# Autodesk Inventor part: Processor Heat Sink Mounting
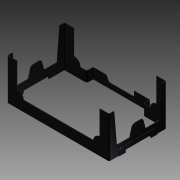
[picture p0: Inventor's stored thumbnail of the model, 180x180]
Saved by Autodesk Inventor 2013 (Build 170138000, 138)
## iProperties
Company: Autodesk Inc.
Created: 2005-11
Part Number: Processor Heat Sink Mounting
Document SubType Name: Modeling
Designer: Autodesk Inc.
Density: 1 g/cm^3
Mass: 1.74353 g
Surface Area: 69.5144 cm^2
Volume: 1.74353 cm^3
Material: Allgemein
Title: Personal Computer
Author: Autodesk Inc.
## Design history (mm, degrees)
sketch "Sketch1"
  geometry: L1 (0, 37.5)-(0, -32.5) reference; L2 (-56, 0)-(56, 0) reference; L3 (-40, 22.5)-(40, 22.5); L4 (40, 22.5)-(40, -22.5); L5 (40, -22.5)-(-40, -22.5); L6 (-40, -22.5)-(-40, 22.5); L7 (-22.5, 22.5)-(22.5, 22.5); L8 (22.5, 22.5)-(22.5, 27.5); L9 (22.5, 27.5)-(-22.5, 27.5); L10 (-22.5, 27.5)-(-22.5, 22.5)
  constraints: 16 end point, 4 parallel, 2 horizontal, 2 perpendicular, 1 point on line, 3 other
  dimensions: "d0" = 80 distance of L3.start L3.end; "d1" = 45 distance of L5.end L3.start; "d2" = 45 distance of L8.end L9.end; "d3" = 5 distance of L9.end L7.start
extrude "Extrusion1" new body sketch "Sketch1" distance "d4" = 32; taper "d5" = 0 deg
fillet "Fillet2" dims "d22" = 1
shell "Shell1" dims "d6" = 0.5
sketch "Sketch2"
  geometry: L1 (80, 32)-(0, 32) reference; L2 (0, 0)-(80, 0) reference; L3 (80, 0)-(80, 32) reference; L4 (7.5, 32)-(7.5, 13); L5 (12.5, 8)-(67.5, 8); L6 (72.5, 13)-(72.5, 32); L7 (7.5, 13)-(24.006, 13); L8 (12.5, 8)-(12.5, 12.458); L9 (72.5, 13)-(51.974, 13); L10 (67.5, 8)-(67.5, 19.427); L11 (40, 38.4)-(40, -6.4) reference; A1 r 5 centre (7.5, 8) between (12.5, 8) and (7.5, 13); A2 r 5 centre (72.5, 8) between (72.5, 13) and (67.5, 8)
  constraints: 14 end point, 6 perpendicular, 4 point on circle, 4 tangent, 3 point on line, 2 centre point, 2 parallel, 1 symmetric about line, 2 other
  dimensions: "d7" = 8 distance between parallel lines of L2 L5; "d8" = 65 distance between parallel lines of L6 L4; "d9" = 5 radius of A1
extrude "Extrusion2" cut sketch "Sketch2" stored distance "d10" = 32; taper "d11" = 0 deg
sketch "Sketch3"
  geometry: L1 (-32, 45)-(-32, 0) reference; L2 (0, 0)-(0, 45) reference; L3 (0, 45)-(-32, 45) reference; L4 (-38.4, 22.5)-(6.4, 22.5) reference; L5 (-32, 41)-(-8, 38.9); L6 (-8, 38.9)-(-8, 28.644); L7 (-8, 28.644)-(-16, 26.5); L8 (-16, 26.5)-(-16, 18.5); L9 (-16, 18.5)-(-8, 16.356); L10 (-8, 16.356)-(-8, 6.1); L11 (-8, 6.1)-(-32, 4)
  constraints: 14 end point, 2 parallel, 2 point on line, 2 symmetric about line, 1 perpendicular, 2 other
  dimensions: "d12" = 8 distance between parallel lines of L2 L6; "d13" = 4 distance from line of L3 L5.start; "d14" = 95 deg angle of L5 L1; "d15" = 8 distance of L7.end L8.end; "d16" = 8 distance between parallel lines of L6 L8; "d17" = 105 deg angle of L7 L6
extrude "Extrusion3" cut sketch "Sketch3" stored distance "d18" = 32; taper "d19" = 0 deg
fillet "Fillet1" dims "d20" = 2, "d21" = 1
sketch "Sketch4"
  geometry: L1 (0, -8)-(43, -8) reference; L2 (21.5, 6.4)-(21.5, -38.4) reference; L3 (9.191, -8)-(11.211, -4.5); L4 (12.077, -4)-(30.5, -4); L5 (31.5, -5)-(31.5, -8); A1 r 1 centre (12.077, -5) between (12.077, -4) and (11.211, -4.5); A2 r 1 centre (30.5, -5) between (31.5, -5) and (30.5, -4); 2 further points
  constraints: 6 end point, 6 point on line, 4 point on circle, 4 tangent, 2 centre point, 2 perpendicular, 1 equal radius, 1 symmetric about line
  dimensions: "d23" = 4 distance of point (31.5, -4) L5.end; "d24" = 120 deg angle of L4 L3; "d25" = 20 distance of point (11.5, -4) point (31.5, -4); "d26" = 1 radius of A1
extrude "Extrusion4" cut sketch "Sketch4" stored distance "d27" = 32; taper "d28" = 0 deg
sketch "Sketch6"
  geometry: L1 (0, 0)-(0, 43) reference; L2 (0, 36.5)-(-3, 36.5); L3 (-5, 34.5)-(-5, 8.5); L4 (-3, 6.5)-(0, 6.5); L5 (0, 6.5)-(0, 36.5); L6 (-38.4, 21.5)-(6.4, 21.5) reference; L7 (-14, 23.965)-(-5, 23.965); L8 (-5, 23.965)-(-5, 23.165); L9 (-5, 23.165)-(-14, 23.165); L10 (-14, 23.165)-(-14, 23.965); L11 (-14, 19.035)-(-5, 19.035); L12 (-5, 19.035)-(-5, 19.835); L13 (-5, 19.835)-(-14, 19.835); L14 (-14, 19.835)-(-14, 19.035); A1 r 2 centre (-14, 23.965) between (-14.518, 25.897) and (-16, 23.965) reference; A2 r 2 centre (-14, 19.035) between (-16, 19.035) and (-14.518, 17.103) reference; A3 r 2 centre (-3, 34.5) between (-3, 36.5) and (-5, 34.5); A4 r 2 centre (-3, 8.5) between (-5, 8.5) and (-3, 6.5); 2 further points
  constraints: 24 end point, 7 point on line, 6 parallel, 4 point on circle, 4 tangent, 3 horizontal, 3 perpendicular, 2 centre point, 1 collinear, 1 equal radius, 1 other
  dimensions: "d29" = 5 distance of L2.start point (-5, 36.5); "d30" = 30 distance of point (-5, 36.5) point (-5, 6.5); "d31" = 0.8 distance of L9.end L7.start; "d32" = 2 radius of A3
extrude "Extrusion5" join sketch "Sketch6" distance "d33" = 0.5; taper "d34" = 0 deg
sketch "Sketch7"
  geometry: L1 (0, 36.5)-(0, 6.5) reference; L2 (-38.4, 21.5)-(6.4, 21.5) reference; L3 (0, 31.5)-(-2, 31.5); L4 (-2, 31.5)-(-2, 11.5); L5 (-2, 11.5)-(0, 11.5); L6 (0, 11.5)-(0, 31.5)
  constraints: 8 end point, 2 parallel, 1 horizontal, 1 perpendicular, 1 point on line, 1 other
  dimensions: "d35" = 2 distance of L3.start L3.end; "d36" = 20 distance of L3.end L4.end
extrude "Extrusion6" cut sketch "Sketch7" stored distance "d37" = 0.5; taper "d38" = 0 deg
mirror "Mirror1"
body "Solid1"
